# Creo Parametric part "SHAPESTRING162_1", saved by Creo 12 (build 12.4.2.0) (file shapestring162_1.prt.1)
Units: Custom; MM, KILOGRAM, SECS

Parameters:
  PTC_WM_ITERATION = "0"
  PTC_WM_VERSION = "-.0"
  PTC_WM_LIFECYCLE_STATE = "In Work"
  PTC_WM_LIFECYCLE = "MO_CADDocument"
  PTC_WM_CREATED_BY = "Maximilian Roepper (Z0017RMS: MO)"
  PTC_WM_CREATED_ON = "18-Sep-26 11:36:42 AM"
  PTC_WM_MODIFIED_BY = "Maximilian Roepper (Z0017RMS: MO)"
  PTC_WM_MODIFIED_ON = "18-Sep-26 11:36:46 AM"
  PDMLINKNUMBER = "PDM000071454808"
  PTC_WM_NAME = "shapestring162_1.prt"
  PTC_WM_NUMBER = "PDM000071454808"

Other parameters: WEIGHT, WEIGHT_FACTOR, WEIGHT_ADD, _MASS_TEMP, _DIFF_TEMP, MC_ERRORS, SUPPLIER

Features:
  1. coordinate system
  2. datum plane "PRT_YZ"
  3. datum plane "PRT_XY"
  4. datum plane "PRT_XZ"
  5. coordinate system
  6. datum axis
  7. datum axis
  8. datum axis
  9. coordinate system
  10. imported feature

Other named items: PRT, SIEMENS_MO, DRW_VIEW_ORG, PRT_X, PRT_Y, PRT_Z, CS0, ROUGH_GROB

Layers: 00_STD_CSYS-KSYS, 01_STD_PLANES-EBENEN, 02_STD_AXES-ACHSEN, 03_STD_CSYS-KSYS, 24_IMPORT_FEAT-IMPORT_KE, INTFCLR

Surfaces: 1 plane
